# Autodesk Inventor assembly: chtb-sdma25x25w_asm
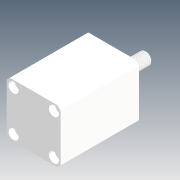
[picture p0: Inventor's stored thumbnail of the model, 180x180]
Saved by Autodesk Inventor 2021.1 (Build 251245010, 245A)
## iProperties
Company: Microsoft
Created: 2018-05
Part Number: chtb-sdma25x25w_asm
Description: STEP AP214
Document SubType Name: Assembly
Designer: user
Title: chtb-sdma25x25w_asm.STEP
Author: Windows
Revision Number: ÈÎºÎ
Sending System: SolidWorks 2015
Preprocessor: SwSTEP 2.0
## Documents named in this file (4)
- D:\Vault_2016\Projekty\Clamptek\Hydraulic\CHTB\CHTB-25\Inventor\chtb-sdma25x25w\chtb-sdma25x25w_asm.iam
- D:\Vault_2016\Projekty\Clamptek\Hydraulic\CHTB\CHTB-25\Inventor\chtb-sdma25x25w\CHTB-25QG.ipt
- D:\Vault_2016\Projekty\Clamptek\Hydraulic\CHTB\CHTB-25\Inventor\chtb-sdma25x25w\CHTB-SDMA25X25NBT.ipt
- D:\Vault_2016\Projekty\Clamptek\Hydraulic\CHTB\CHTB-25\Inventor\chtb-sdma25x25w\CHTB-SDMA25X25WHSG.ipt
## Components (3 placed, 3 different names)
1. CHTB-25QG_1
2. CHTB-SDMA25X25NBT_2
3. CHTB-SDMA25X25WHSG_3
